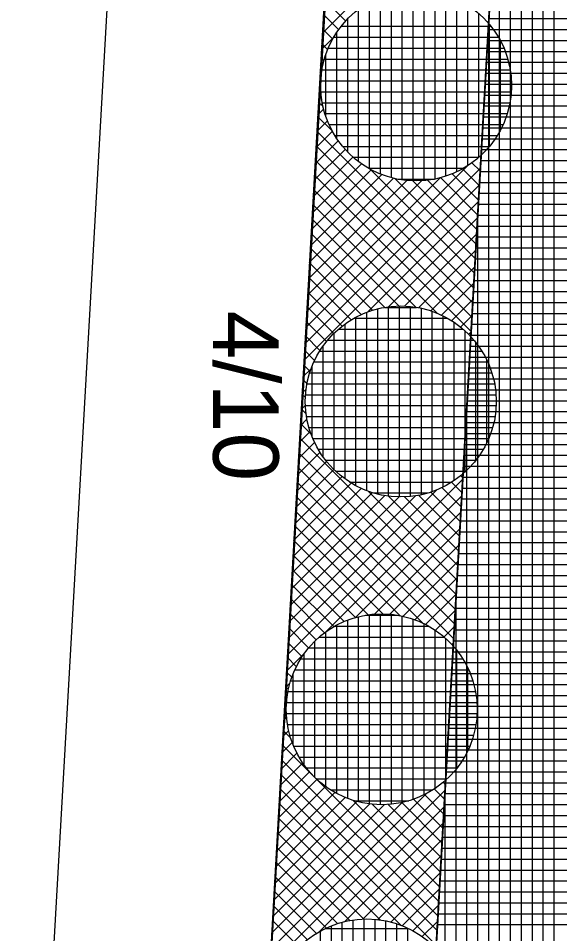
# Model space of a CAD drawing. Extents: x -565346 to -564154, y -1097386 to -1095620.
# Drawn here: x -564309.21 to -564299.29, y -1097277.36 to -1097260.58 of the extents above; entities that cross this region are included whole.
import ezdxf

# ---------------------------------------------------------------- set-up
doc = ezdxf.new("R2010")
doc.units = 0
for name, color, linetype in [('Vrstva 1', 7, 'Continuous'), ('Vrstva 40', 7, 'Continuous'), ('Vrstva 41', 7, 'Continuous'), ('Vrstva 42', 7, 'Continuous'), ('Vrstva 43', 7, 'Continuous'), ('Vrstva 44', 7, 'Continuous')]:
    doc.layers.add(name, color=color, linetype=linetype)

msp = doc.modelspace()

# ---------------------------------------------------------------- linework, layer by layer
at = {"layer": 'Vrstva 1'}
for p, q in [((-564307.09, -1097322.09), (-564296.5, -1097135.53)), ((-564305.71, -1097227.33), (-564309.21, -1097289.05))]:
    msp.add_line(p, q, dxfattribs=at)
at = {"layer": 'Vrstva 41'}
msp.add_lwpolyline([(-564307.383, -1097332.191), (-564304.399, -1097332.838), (-564304.096, -1097322.37), (-564303.226, -1097307.04), (-564296.016, -1097180.02), (-564294.347, -1097150.646), (-564297.42, -1097150.37), (-564307.09, -1097322.09)], close=True, dxfattribs=at)
at = {"layer": 'Vrstva 42'}
for p, q in [((-564301.09, -1097258.309), (-564303.642, -1097260.861)), ((-564303.607, -1097260.239), (-564303.214, -1097260.633)), ((-564303.622, -1097260.507), (-564303.342, -1097260.787)), ((-564300.592, -1097260.639), (-564300.611, -1097260.658)), ((-564303.637, -1097260.775), (-564303.451, -1097260.961)), ((-564303.442, -1097260.944), (-564303.659, -1097261.16)), ((-564303.652, -1097261.042), (-564303.542, -1097261.153)), ((-564303.667, -1097261.31), (-564303.613, -1097261.365)), ((-564303.625, -1097261.409), (-564303.676, -1097261.46)), ((-564303.682, -1097261.578), (-564303.659, -1097261.601)), ((-564303.697, -1097261.846), (-564303.671, -1097261.872)), ((-564303.67, -1097261.737), (-564303.693, -1097261.76)), ((-564303.662, -1097262.012), (-564303.71, -1097262.059)), ((-564303.713, -1097262.114), (-564303.632, -1097262.195)), ((-564303.728, -1097262.381), (-564303.461, -1097262.648)), ((-564303.617, -1097262.249), (-564303.726, -1097262.359)), ((-564303.547, -1097262.463), (-564303.743, -1097262.659)), ((-564303.457, -1097262.656), (-564303.76, -1097262.959)), ((-564303.743, -1097262.649), (-564300.869, -1097265.522)), ((-564303.349, -1097262.83), (-564303.777, -1097263.258)), ((-564303.222, -1097262.987), (-564303.794, -1097263.558)), ((-564303.758, -1097262.917), (-564300.885, -1097265.79)), ((-564303.08, -1097263.127), (-564303.811, -1097263.858)), ((-564303.773, -1097263.185), (-564300.9, -1097266.058)), ((-564300.743, -1097263.104), (-564300.733, -1097263.114)), ((-564300.745, -1097263.338), (-564303.963, -1097266.555)), ((-564300.967, -1097263.277), (-564303.946, -1097266.256)), ((-564302.745, -1097263.358), (-564303.845, -1097264.457)), ((-564302.921, -1097263.251), (-564303.828, -1097264.157)), ((-564302.758, -1097263.351), (-564300.854, -1097265.255)), ((-564301.071, -1097263.341), (-564300.763, -1097263.649)), ((-564300.897, -1097263.232), (-564300.748, -1097263.381)), ((-564301.476, -1097263.503), (-564303.929, -1097265.956)), ((-564301.814, -1097263.558), (-564303.912, -1097265.656)), ((-564302.086, -1097263.547), (-564303.895, -1097265.356)), ((-564302.335, -1097263.513), (-564303.878, -1097265.057)), ((-564302.55, -1097263.446), (-564303.861, -1097264.757)), ((-564303.788, -1097263.452), (-564300.915, -1097266.325)), ((-564302.305, -1097263.522), (-564300.839, -1097264.987)), ((-564301.986, -1097263.558), (-564300.824, -1097264.719)), ((-564301.711, -1097263.549), (-564300.809, -1097264.452)), ((-564301.475, -1097263.503), (-564300.793, -1097264.184)), ((-564301.263, -1097263.432), (-564300.778, -1097263.917)), ((-564300.762, -1097263.638), (-564303.98, -1097266.855)), ((-564303.803, -1097263.72), (-564301.534, -1097265.989)), ((-564303.818, -1097263.988), (-564301.928, -1097265.878)), ((-564300.779, -1097263.938), (-564302.804, -1097265.963)), ((-564303.833, -1097264.256), (-564302.233, -1097265.856)), ((-564300.796, -1097264.238), (-564302.429, -1097265.871)), ((-564303.848, -1097264.523), (-564302.491, -1097265.88)), ((-564300.813, -1097264.537), (-564302.134, -1097265.858)), ((-564303.863, -1097264.791), (-564302.721, -1097265.933)), ((-564300.83, -1097264.837), (-564301.879, -1097265.886)), ((-564303.878, -1097265.059), (-564302.927, -1097266.011)), ((-564300.847, -1097265.137), (-564301.654, -1097265.943)), ((-564303.894, -1097265.327), (-564303.111, -1097266.109)), ((-564300.864, -1097265.437), (-564301.453, -1097266.025)), ((-564303.909, -1097265.594), (-564303.278, -1097266.225)), ((-564300.882, -1097265.737), (-564301.271, -1097266.126)), ((-564303.924, -1097265.862), (-564303.428, -1097266.357)), ((-564300.899, -1097266.037), (-564301.106, -1097266.244)), ((-564303.939, -1097266.13), (-564303.563, -1097266.505)), ((-564303.954, -1097266.398), (-564303.682, -1097266.67)), ((-564300.916, -1097266.337), (-564300.958, -1097266.379)), ((-564303.969, -1097266.666), (-564303.783, -1097266.852)), ((-564303.845, -1097267.004), (-564303.996, -1097267.155)), ((-564303.984, -1097266.933), (-564303.864, -1097267.053)), ((-564303.999, -1097267.201), (-564303.922, -1097267.278)), ((-564303.937, -1097267.379), (-564304.013, -1097267.454)), ((-564304.014, -1097267.469), (-564303.95, -1097267.533)), ((-564303.95, -1097267.674), (-564304.03, -1097267.754)), ((-564304.029, -1097267.737), (-564303.938, -1097267.828)), ((-564303.922, -1097267.929), (-564304.047, -1097268.054)), ((-564304.044, -1097268.004), (-564303.846, -1097268.202)), ((-564303.865, -1097268.154), (-564304.064, -1097268.354)), ((-564303.783, -1097268.355), (-564304.081, -1097268.653)), ((-564304.059, -1097268.272), (-564301.188, -1097271.143)), ((-564303.682, -1097268.537), (-564304.098, -1097268.953)), ((-564304.074, -1097268.54), (-564301.204, -1097271.411)), ((-564303.564, -1097268.702), (-564304.115, -1097269.253)), ((-564303.429, -1097268.85), (-564304.131, -1097269.552)), ((-564304.09, -1097268.808), (-564301.219, -1097271.678)), ((-564301.069, -1097269.035), (-564304.283, -1097272.25)), ((-564303.279, -1097268.983), (-564304.148, -1097269.852)), ((-564304.105, -1097269.075), (-564301.234, -1097271.946)), ((-564301.27, -1097269.082), (-564301.082, -1097269.27)), ((-564301.105, -1097268.963), (-564301.067, -1097269.002)), ((-564301.536, -1097269.22), (-564304.266, -1097271.95)), ((-564302.928, -1097269.197), (-564304.182, -1097270.452)), ((-564303.112, -1097269.099), (-564304.165, -1097270.152)), ((-564302.802, -1097269.246), (-564301.173, -1097270.875)), ((-564301.653, -1097269.264), (-564301.112, -1097269.805)), ((-564301.452, -1097269.183), (-564301.097, -1097269.537)), ((-564301.929, -1097269.33), (-564304.25, -1097271.651)), ((-564302.233, -1097269.351), (-564304.233, -1097271.351)), ((-564302.489, -1097269.324), (-564304.216, -1097271.051)), ((-564302.722, -1097269.274), (-564304.199, -1097270.751)), ((-564304.12, -1097269.343), (-564301.793, -1097271.67)), ((-564301.086, -1097269.335), (-564303.57, -1097271.82)), ((-564302.436, -1097269.33), (-564301.158, -1097270.608)), ((-564302.133, -1097269.35), (-564301.143, -1097270.34)), ((-564301.878, -1097269.322), (-564301.128, -1097270.072)), ((-564304.135, -1097269.611), (-564302.218, -1097271.528)), ((-564301.103, -1097269.635), (-564303.03, -1097271.562)), ((-564304.15, -1097269.879), (-564302.533, -1097271.495)), ((-564301.12, -1097269.935), (-564302.686, -1097271.501)), ((-564304.165, -1097270.146), (-564302.798, -1097271.513)), ((-564301.137, -1097270.235), (-564302.404, -1097271.502)), ((-564304.18, -1097270.414), (-564303.031, -1097271.563)), ((-564301.154, -1097270.535), (-564302.159, -1097271.54)), ((-564304.195, -1097270.682), (-564303.241, -1097271.636)), ((-564301.171, -1097270.835), (-564301.943, -1097271.607)), ((-564304.21, -1097270.95), (-564303.431, -1097271.729)), ((-564304.225, -1097271.217), (-564303.6, -1097271.842)), ((-564301.188, -1097271.134), (-564301.747, -1097271.693)), ((-564301.205, -1097271.434), (-564301.57, -1097271.799)), ((-564304.24, -1097271.485), (-564303.753, -1097271.972)), ((-564304.255, -1097271.753), (-564303.891, -1097272.118)), ((-564301.222, -1097271.734), (-564301.41, -1097271.922)), ((-564304.27, -1097272.021), (-564304.012, -1097272.279)), ((-564301.239, -1097272.034), (-564301.266, -1097272.061)), ((-564303.978, -1097272.228), (-564304.3, -1097272.55)), ((-564304.286, -1097272.289), (-564304.116, -1097272.459)), ((-564304.301, -1097272.556), (-564304.2, -1097272.657)), ((-564304.236, -1097272.768), (-564304.317, -1097272.849)), ((-564304.316, -1097272.824), (-564304.265, -1097272.875)), ((-564304.297, -1097273.112), (-564304.334, -1097273.149)), ((-564304.331, -1097273.092), (-564304.298, -1097273.125)), ((-564304.296, -1097273.394), (-564304.351, -1097273.449)), ((-564304.346, -1097273.36), (-564304.295, -1097273.411)), ((-564304.258, -1097273.639), (-564304.368, -1097273.749)), ((-564304.361, -1097273.627), (-564304.223, -1097273.765)), ((-564304.191, -1097273.855), (-564304.385, -1097274.048)), ((-564304.376, -1097273.895), (-564301.507, -1097276.764)), ((-564304.105, -1097274.051), (-564304.402, -1097274.348)), ((-564303.999, -1097274.228), (-564304.418, -1097274.648)), ((-564304.391, -1097274.163), (-564301.523, -1097277.031)), ((-564303.876, -1097274.388), (-564304.435, -1097274.947)), ((-564304.406, -1097274.431), (-564301.538, -1097277.299)), ((-564303.737, -1097274.532), (-564304.452, -1097275.247)), ((-564301.428, -1097274.581), (-564301.386, -1097274.623)), ((-564301.392, -1097274.733), (-564304.604, -1097277.945)), ((-564301.726, -1097274.784), (-564304.587, -1097277.645)), ((-564303.409, -1097274.77), (-564304.486, -1097275.847)), ((-564303.582, -1097274.66), (-564304.469, -1097275.547)), ((-564304.421, -1097274.698), (-564301.553, -1097277.567)), ((-564301.589, -1097274.702), (-564301.401, -1097274.89)), ((-564302.178, -1097274.953), (-564304.57, -1097277.345)), ((-564303.006, -1097274.932), (-564304.52, -1097276.446)), ((-564303.218, -1097274.861), (-564304.503, -1097276.146)), ((-564304.436, -1097274.966), (-564302.202, -1097277.201)), ((-564303.075, -1097274.913), (-564301.492, -1097276.496)), ((-564302.185, -1097274.955), (-564301.447, -1097275.693)), ((-564301.967, -1097274.89), (-564301.431, -1097275.425)), ((-564301.769, -1097274.806), (-564301.416, -1097275.158)), ((-564302.499, -1097274.991), (-564304.553, -1097277.045)), ((-564302.763, -1097274.972), (-564304.537, -1097276.746)), ((-564301.409, -1097275.033), (-564303.69, -1097277.313)), ((-564302.73, -1097274.976), (-564301.477, -1097276.228)), ((-564302.435, -1097274.988), (-564301.462, -1097275.961)), ((-564304.451, -1097275.234), (-564302.582, -1097277.103)), ((-564301.426, -1097275.332), (-564303.226, -1097277.132)), ((-564304.466, -1097275.502), (-564302.881, -1097277.087)), ((-564301.443, -1097275.632), (-564302.899, -1097277.088)), ((-564304.482, -1097275.769), (-564303.137, -1097277.114)), ((-564301.46, -1097275.932), (-564302.625, -1097277.097)), ((-564304.497, -1097276.037), (-564303.364, -1097277.17)), ((-564304.512, -1097276.305), (-564303.566, -1097277.25)), ((-564301.477, -1097276.232), (-564302.387, -1097277.142)), ((-564304.527, -1097276.573), (-564303.749, -1097277.351)), ((-564301.494, -1097276.532), (-564302.174, -1097277.211)), ((-564304.542, -1097276.841), (-564303.914, -1097277.468)), ((-564301.511, -1097276.832), (-564301.981, -1097277.302)), ((-564304.557, -1097277.108), (-564304.063, -1097277.602)), ((-564301.528, -1097277.132), (-564301.807, -1097277.41))]:
    msp.add_line(p, q, dxfattribs=at)
at = {"layer": 'Vrstva 43'}
for p, q in [((-564299.39, -1097326.67), (-564299.39, -1097239.473)), ((-564299.59, -1097327.047), (-564299.59, -1097242.996)), ((-564299.79, -1097327.423), (-564299.79, -1097246.519)), ((-564299.99, -1097327.799), (-564299.99, -1097250.041)), ((-564300.19, -1097328.175), (-564300.19, -1097253.564)), ((-564300.39, -1097328.551), (-564300.39, -1097257.087)), ((-564300.59, -1097328.928), (-564300.59, -1097260.61)), ((-564300.589, -1097260.59), (-564293.578, -1097260.59)), ((-564300.6, -1097260.79), (-564293.589, -1097260.79)), ((-564300.612, -1097260.99), (-564293.601, -1097260.99)), ((-564300.623, -1097261.19), (-564293.612, -1097261.19)), ((-564300.634, -1097261.39), (-564293.623, -1097261.39)), ((-564300.646, -1097261.59), (-564293.635, -1097261.59)), ((-564300.657, -1097261.79), (-564293.646, -1097261.79)), ((-564300.668, -1097261.99), (-564293.657, -1097261.99)), ((-564300.68, -1097262.19), (-564293.669, -1097262.19)), ((-564300.691, -1097262.39), (-564293.68, -1097262.39)), ((-564300.702, -1097262.59), (-564293.692, -1097262.59)), ((-564300.714, -1097262.79), (-564293.703, -1097262.79)), ((-564300.725, -1097262.99), (-564293.714, -1097262.99)), ((-564300.736, -1097263.19), (-564293.726, -1097263.19)), ((-564300.748, -1097263.39), (-564293.737, -1097263.39)), ((-564300.759, -1097263.59), (-564293.748, -1097263.59)), ((-564300.771, -1097263.79), (-564293.76, -1097263.79)), ((-564300.782, -1097263.99), (-564293.771, -1097263.99)), ((-564300.793, -1097264.19), (-564293.782, -1097264.19)), ((-564300.79, -1097329.304), (-564300.79, -1097264.133)), ((-564300.805, -1097264.39), (-564293.794, -1097264.39)), ((-564300.816, -1097264.59), (-564293.805, -1097264.59)), ((-564300.827, -1097264.79), (-564293.816, -1097264.79)), ((-564300.839, -1097264.99), (-564293.828, -1097264.99)), ((-564300.85, -1097265.19), (-564293.839, -1097265.19)), ((-564300.861, -1097265.39), (-564293.85, -1097265.39)), ((-564300.873, -1097265.59), (-564293.862, -1097265.59)), ((-564300.884, -1097265.79), (-564293.873, -1097265.79)), ((-564300.895, -1097265.99), (-564293.884, -1097265.99)), ((-564300.907, -1097266.19), (-564293.896, -1097266.19)), ((-564300.918, -1097266.39), (-564293.907, -1097266.39)), ((-564300.93, -1097266.59), (-564293.919, -1097266.59)), ((-564300.941, -1097266.79), (-564293.93, -1097266.79)), ((-564300.952, -1097266.99), (-564293.941, -1097266.99)), ((-564300.964, -1097267.19), (-564293.953, -1097267.19)), ((-564300.975, -1097267.39), (-564293.964, -1097267.39)), ((-564300.99, -1097329.68), (-564300.99, -1097267.655)), ((-564300.986, -1097267.59), (-564293.975, -1097267.59)), ((-564300.998, -1097267.79), (-564293.987, -1097267.79)), ((-564301.009, -1097267.99), (-564293.998, -1097267.99)), ((-564301.02, -1097268.19), (-564294.009, -1097268.19)), ((-564301.032, -1097268.39), (-564294.021, -1097268.39)), ((-564301.043, -1097268.59), (-564294.032, -1097268.59)), ((-564301.054, -1097268.79), (-564294.043, -1097268.79)), ((-564301.066, -1097268.99), (-564294.055, -1097268.99)), ((-564301.077, -1097269.19), (-564294.066, -1097269.19)), ((-564301.088, -1097269.39), (-564294.077, -1097269.39)), ((-564301.1, -1097269.59), (-564294.089, -1097269.59)), ((-564301.111, -1097269.79), (-564294.1, -1097269.79)), ((-564301.123, -1097269.99), (-564294.111, -1097269.99)), ((-564301.134, -1097270.19), (-564294.123, -1097270.19)), ((-564301.145, -1097270.39), (-564294.134, -1097270.39)), ((-564301.157, -1097270.59), (-564294.146, -1097270.59)), ((-564301.168, -1097270.79), (-564294.157, -1097270.79)), ((-564301.179, -1097270.99), (-564294.168, -1097270.99)), ((-564301.191, -1097271.19), (-564294.18, -1097271.19)), ((-564301.19, -1097330.056), (-564301.19, -1097271.178)), ((-564301.202, -1097271.39), (-564294.191, -1097271.39)), ((-564301.213, -1097271.59), (-564294.202, -1097271.59)), ((-564301.225, -1097271.79), (-564294.214, -1097271.79)), ((-564301.236, -1097271.99), (-564294.225, -1097271.99)), ((-564301.247, -1097272.19), (-564294.236, -1097272.19)), ((-564301.259, -1097272.39), (-564294.248, -1097272.39)), ((-564301.27, -1097272.59), (-564294.259, -1097272.59)), ((-564301.282, -1097272.79), (-564294.27, -1097272.79)), ((-564301.293, -1097272.99), (-564294.282, -1097272.99)), ((-564301.304, -1097273.19), (-564294.293, -1097273.19)), ((-564301.316, -1097273.39), (-564294.304, -1097273.39)), ((-564301.327, -1097273.59), (-564294.316, -1097273.59)), ((-564301.338, -1097273.79), (-564294.327, -1097273.79)), ((-564301.35, -1097273.99), (-564294.339, -1097273.99)), ((-564301.361, -1097274.19), (-564294.35, -1097274.19)), ((-564301.372, -1097274.39), (-564294.361, -1097274.39)), ((-564301.384, -1097274.59), (-564294.373, -1097274.59)), ((-564301.395, -1097274.79), (-564294.384, -1097274.79)), ((-564301.39, -1097330.432), (-564301.39, -1097274.701)), ((-564301.406, -1097274.99), (-564294.395, -1097274.99)), ((-564301.418, -1097275.19), (-564294.407, -1097275.19)), ((-564301.429, -1097275.39), (-564294.418, -1097275.39)), ((-564301.44, -1097275.59), (-564294.429, -1097275.59)), ((-564301.452, -1097275.79), (-564294.441, -1097275.79)), ((-564301.463, -1097275.99), (-564294.452, -1097275.99)), ((-564301.475, -1097276.19), (-564294.463, -1097276.19)), ((-564301.486, -1097276.39), (-564294.475, -1097276.39)), ((-564301.497, -1097276.59), (-564294.486, -1097276.59)), ((-564301.509, -1097276.79), (-564294.497, -1097276.79)), ((-564301.52, -1097276.99), (-564294.509, -1097276.99)), ((-564301.531, -1097277.19), (-564294.52, -1097277.19))]:
    msp.add_line(p, q, dxfattribs=at)
msp.add_lwpolyline([(-564283.37, -1096906.18), (-564284.87, -1096930.83), (-564282.373, -1096930.972), (-564294.286, -1097140.634), (-564296.782, -1097140.492), (-564297.42, -1097150.37), (-564294.347, -1097150.646), (-564303.226, -1097307.04), (-564304.096, -1097322.37), (-564304.399, -1097332.838), (-564302.848, -1097333.175), (-564297.082, -1097322.329), (-564293.197, -1097253.877), (-564289.027, -1097180.417), (-564287.358, -1097151.043), (-564285.364, -1097151.156), (-564284.798, -1097141.172), (-564286.791, -1097141.059), (-564274.888, -1096931.397), (-564272.899, -1096931.51), (-564271.475, -1096906.55)], dxfattribs=at)
at = {"layer": 'Vrstva 44'}
for p, q in [((-564302.58, -1097260.194), (-564302.58, -1097263.436)), ((-564302.38, -1097260.126), (-564302.38, -1097263.502)), ((-564302.18, -1097260.085), (-564302.18, -1097263.544)), ((-564301.98, -1097260.067), (-564301.98, -1097263.563)), ((-564301.78, -1097260.072), (-564301.78, -1097263.557)), ((-564301.58, -1097260.099), (-564301.58, -1097263.528)), ((-564301.38, -1097260.151), (-564301.38, -1097263.476)), ((-564302.78, -1097260.291), (-564302.78, -1097263.337)), ((-564301.18, -1097260.232), (-564301.18, -1097263.398)), ((-564300.98, -1097260.341), (-564300.98, -1097263.287)), ((-564302.98, -1097260.421), (-564302.98, -1097263.207)), ((-564300.78, -1097260.491), (-564300.78, -1097263.138)), ((-564303.18, -1097260.6), (-564303.18, -1097263.028)), ((-564300.58, -1097260.691), (-564300.58, -1097262.934)), ((-564303.38, -1097260.849), (-564303.38, -1097262.779)), ((-564303.294, -1097260.73), (-564300.551, -1097260.73)), ((-564303.432, -1097260.93), (-564300.414, -1097260.93)), ((-564300.38, -1097260.989), (-564300.38, -1097262.637)), ((-564303.531, -1097261.13), (-564300.312, -1097261.13)), ((-564303.602, -1097261.33), (-564300.243, -1097261.33)), ((-564303.58, -1097261.257), (-564303.58, -1097262.375)), ((-564303.648, -1097261.53), (-564300.198, -1097261.53)), ((-564300.18, -1097261.673), (-564300.18, -1097261.964)), ((-564303.67, -1097261.73), (-564300.176, -1097261.73)), ((-564303.667, -1097261.93), (-564300.176, -1097261.93)), ((-564303.642, -1097262.13), (-564300.202, -1097262.13)), ((-564303.593, -1097262.33), (-564300.252, -1097262.33)), ((-564303.519, -1097262.53), (-564300.327, -1097262.53)), ((-564303.411, -1097262.73), (-564300.431, -1097262.73)), ((-564303.269, -1097262.93), (-564300.577, -1097262.93)), ((-564303.073, -1097263.13), (-564300.77, -1097263.13)), ((-564302.793, -1097263.33), (-564301.051, -1097263.33)), ((-564302.258, -1097263.53), (-564301.587, -1097263.53)), ((-564302.63, -1097265.909), (-564302.63, -1097269.3)), ((-564302.499, -1097265.88), (-564301.913, -1097265.88)), ((-564302.43, -1097265.871), (-564302.43, -1097269.339)), ((-564302.23, -1097265.856), (-564302.23, -1097269.353)), ((-564302.03, -1097265.863), (-564302.03, -1097269.344)), ((-564301.83, -1097265.895), (-564301.83, -1097269.312)), ((-564303.03, -1097266.064), (-564303.03, -1097269.144)), ((-564302.83, -1097265.971), (-564302.83, -1097269.236)), ((-564301.63, -1097265.952), (-564301.63, -1097269.257)), ((-564301.43, -1097266.036), (-564301.43, -1097269.174)), ((-564303.23, -1097266.19), (-564303.23, -1097269.018)), ((-564303.058, -1097266.08), (-564301.344, -1097266.08)), ((-564301.23, -1097266.149), (-564301.23, -1097269.057)), ((-564303.43, -1097266.36), (-564303.43, -1097268.849)), ((-564303.343, -1097266.28), (-564301.06, -1097266.28)), ((-564301.03, -1097266.307), (-564301.03, -1097268.904)), ((-564303.541, -1097266.48), (-564300.861, -1097266.48)), ((-564300.83, -1097266.52), (-564300.83, -1097268.688)), ((-564303.686, -1097266.68), (-564300.718, -1097266.68)), ((-564303.63, -1097266.595), (-564303.63, -1097268.615)), ((-564303.794, -1097266.88), (-564300.61, -1097266.88)), ((-564300.63, -1097266.839), (-564300.63, -1097268.373)), ((-564303.869, -1097267.08), (-564300.533, -1097267.08)), ((-564303.83, -1097266.968), (-564303.83, -1097268.24)), ((-564303.92, -1097267.28), (-564300.484, -1097267.28)), ((-564303.946, -1097267.48), (-564300.458, -1097267.48)), ((-564303.95, -1097267.68), (-564300.455, -1097267.68)), ((-564303.928, -1097267.88), (-564300.474, -1097267.88)), ((-564303.884, -1097268.08), (-564300.519, -1097268.08)), ((-564303.814, -1097268.28), (-564300.59, -1097268.28)), ((-564303.716, -1097268.48), (-564300.688, -1097268.48)), ((-564303.579, -1097268.68), (-564300.823, -1097268.68)), ((-564303.398, -1097268.88), (-564301.006, -1097268.88)), ((-564303.141, -1097269.08), (-564301.264, -1097269.08)), ((-564302.704, -1097269.28), (-564301.704, -1097269.28)), ((-564303.18, -1097271.611), (-564303.18, -1097274.876)), ((-564302.98, -1097271.549), (-564302.98, -1097274.94)), ((-564302.848, -1097271.52), (-564302.264, -1097271.52)), ((-564302.78, -1097271.511), (-564302.78, -1097274.979)), ((-564302.58, -1097271.496), (-564302.58, -1097274.993)), ((-564302.38, -1097271.503), (-564302.38, -1097274.984)), ((-564302.18, -1097271.535), (-564302.18, -1097274.952)), ((-564301.98, -1097271.592), (-564301.98, -1097274.897)), ((-564303.407, -1097271.72), (-564301.694, -1097271.72)), ((-564303.38, -1097271.705), (-564303.38, -1097274.784)), ((-564301.78, -1097271.675), (-564301.78, -1097274.814)), ((-564303.693, -1097271.92), (-564301.41, -1097271.92)), ((-564303.58, -1097271.83), (-564303.58, -1097274.658)), ((-564301.58, -1097271.789), (-564301.58, -1097274.697)), ((-564301.38, -1097271.947), (-564301.38, -1097274.544)), ((-564303.78, -1097272), (-564303.78, -1097274.489)), ((-564303.98, -1097272.235), (-564303.98, -1097274.255)), ((-564303.891, -1097272.12), (-564301.21, -1097272.12)), ((-564301.18, -1097272.16), (-564301.18, -1097274.329)), ((-564304.036, -1097272.32), (-564301.068, -1097272.32)), ((-564304.18, -1097272.608), (-564304.18, -1097273.879)), ((-564304.144, -1097272.52), (-564300.96, -1097272.52)), ((-564300.98, -1097272.479), (-564300.98, -1097274.013)), ((-564304.219, -1097272.72), (-564300.883, -1097272.72)), ((-564304.269, -1097272.92), (-564300.834, -1097272.92)), ((-564304.296, -1097273.12), (-564300.808, -1097273.12)), ((-564304.3, -1097273.32), (-564300.805, -1097273.32)), ((-564304.278, -1097273.52), (-564300.824, -1097273.52)), ((-564304.233, -1097273.72), (-564300.869, -1097273.72)), ((-564304.164, -1097273.92), (-564300.939, -1097273.92)), ((-564304.066, -1097274.12), (-564301.038, -1097274.12)), ((-564303.929, -1097274.32), (-564301.173, -1097274.32)), ((-564303.748, -1097274.52), (-564301.355, -1097274.52)), ((-564303.491, -1097274.72), (-564301.614, -1097274.72)), ((-564303.054, -1097274.92), (-564302.053, -1097274.92)), ((-564303.28, -1097277.146), (-564303.28, -1097280.522)), ((-564303.08, -1097277.105), (-564303.08, -1097280.564)), ((-564302.88, -1097277.087), (-564302.88, -1097280.583)), ((-564302.68, -1097277.092), (-564302.68, -1097280.577)), ((-564302.48, -1097277.119), (-564302.48, -1097280.548)), ((-564303.68, -1097277.311), (-564303.68, -1097280.358)), ((-564303.585, -1097277.26), (-564302.063, -1097277.26)), ((-564303.48, -1097277.213), (-564303.48, -1097280.456)), ((-564302.28, -1097277.172), (-564302.28, -1097280.496)), ((-564302.08, -1097277.252), (-564302.08, -1097280.418))]:
    msp.add_line(p, q, dxfattribs=at)
for centre in [(-564301.922, -1097261.814), (-564302.202, -1097267.604), (-564302.551, -1097273.244), (-564302.823, -1097278.834)]:
    msp.add_circle(centre, 1.75, dxfattribs=at)

# ---------------------------------------------------------------- texts
at = {"layer": 'Vrstva 40'}
msp.add_text('4/10', height=1.2, rotation=270, dxfattribs=at).set_placement((-564305.64, -1097265.94))

doc.saveas('drawing.dxf')
